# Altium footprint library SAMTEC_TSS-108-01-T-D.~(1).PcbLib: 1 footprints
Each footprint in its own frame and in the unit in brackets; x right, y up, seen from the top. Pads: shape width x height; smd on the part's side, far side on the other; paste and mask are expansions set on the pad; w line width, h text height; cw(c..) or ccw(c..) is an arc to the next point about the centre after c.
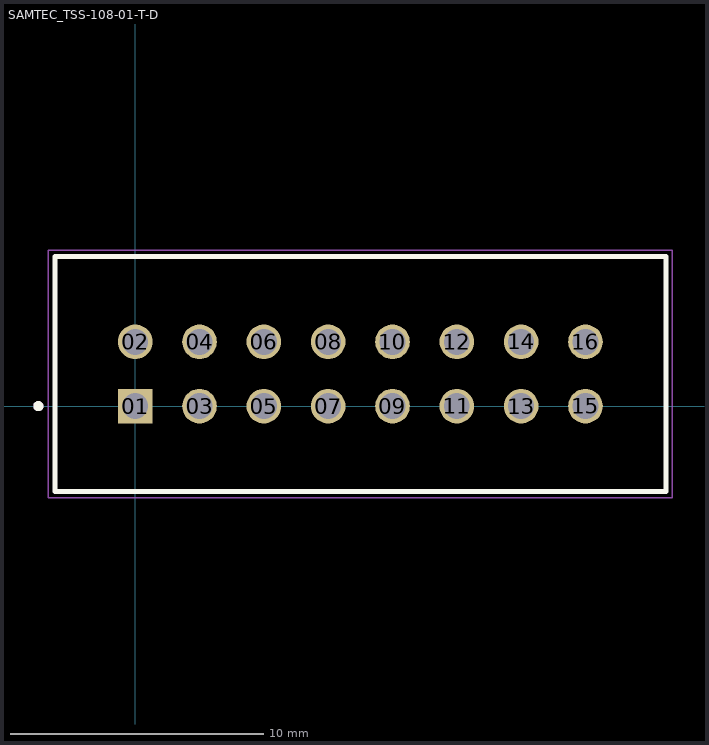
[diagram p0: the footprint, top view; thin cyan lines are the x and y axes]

## SAMTEC_TSS-108-01-T-D [mm]
pads (16):
  rect 1.37x1.37 hole 1.02: 01(0,0)
  round 1.37 hole 1.02: 02(0,2.54) 03(2.54,0) 04(2.54,2.54) 05(5.08,0) 06(5.08,2.54) 07(7.62,0) 08(7.62,2.54) 09(10.16,0) 10(10.16,2.54) 11(12.7,0) 12(12.7,2.54) 13(15.24,0) 14(15.24,2.54) 15(17.78,0) 16(17.78,2.54)
Top Overlay:
  circle w0.2: c-3.825,0 r0.1
  lines w0.2: -3.175,-3.365 -3.175,5.905 20.955,5.905 20.955,-3.365 -3.175,-3.365
Mechanical 13:
  circle w0.2: c-3.825,0 r0.1
  lines w0.1: -3.175,-3.365 -3.175,5.905 20.955,5.905 20.955,-3.365 -3.175,-3.365
Mechanical 15:
  lines w0.05: -3.425,-3.615 -3.425,6.155 21.205,6.155 21.205,-3.615 -3.425,-3.615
